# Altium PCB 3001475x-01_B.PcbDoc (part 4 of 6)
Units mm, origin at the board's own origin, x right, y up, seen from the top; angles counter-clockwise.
Board outline 335 x 91 mm, 12 copper layers (Top Layer, L2 GND, Layer 3, L4 GND, Layer 5, L6 PWR, L7 3V3, Layer 8, L9 GND, Layer 10, L11 GND, Bottom Layer), stack 1.59 mm thick; 339 components, 431 nets, 1732 pads, 1526 vias.
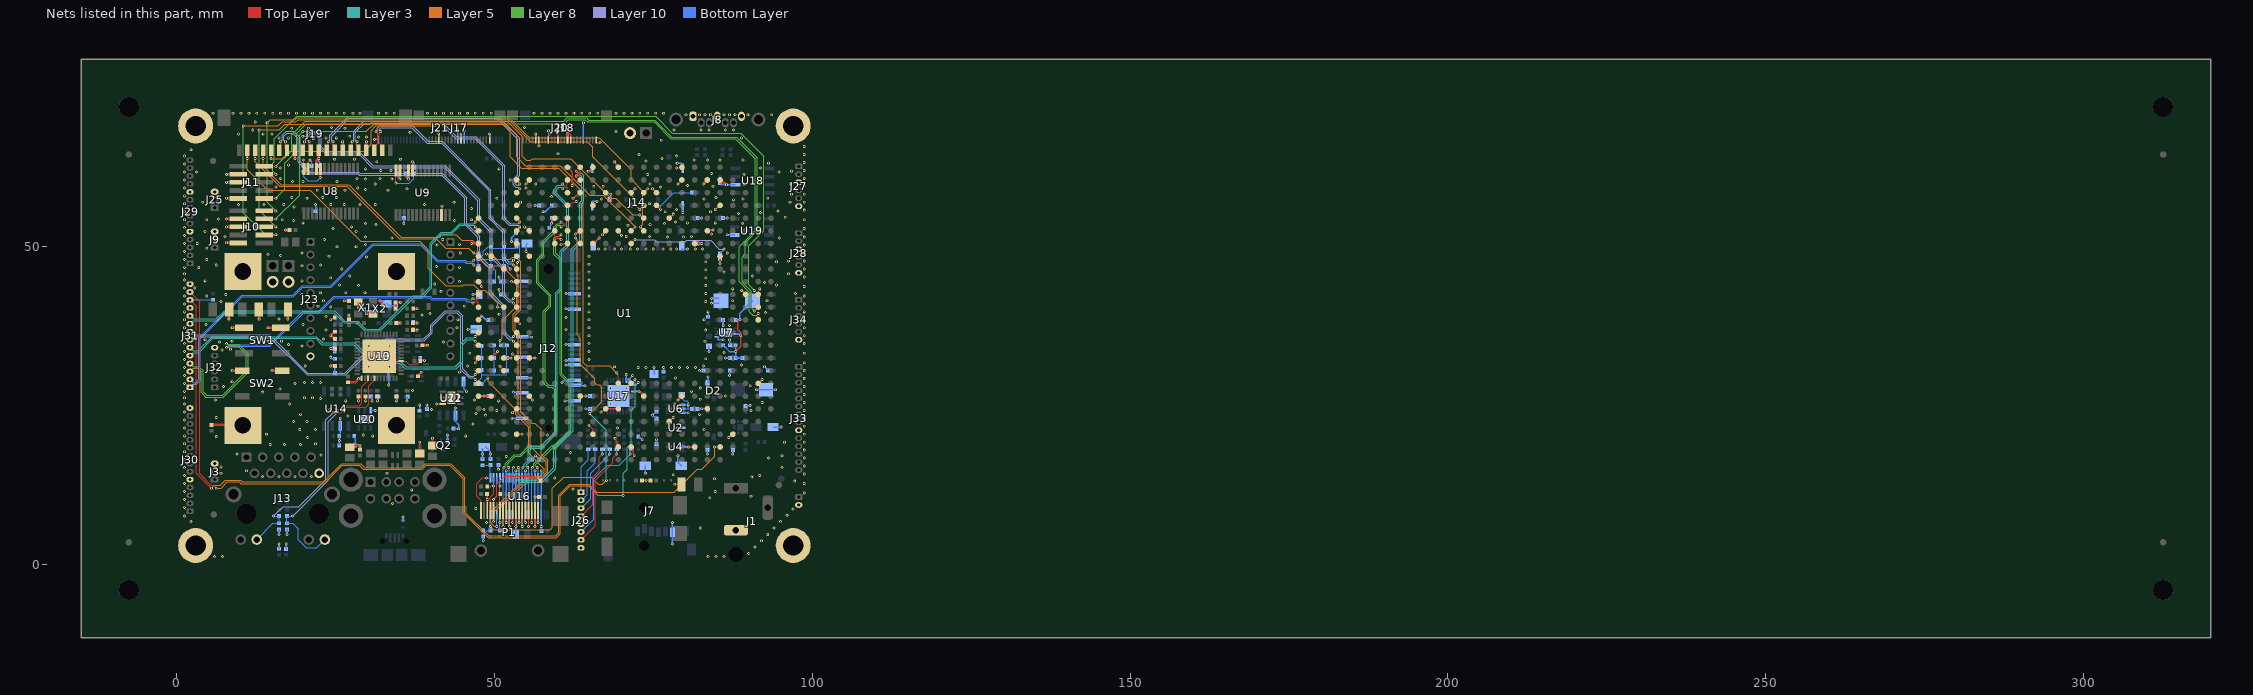
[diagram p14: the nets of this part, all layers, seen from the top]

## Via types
v1: diameter 0.45, hole 0.2, Top Layer to Bottom Layer, 1511 vias
v2: diameter 0.5, hole 0.2, Top Layer to Bottom Layer, 14 vias
v3: diameter 0.45/0.45/0.45/0.45/0.45/0.45/0.45/0.45/0.45/0.45/0.45/0.45 (per signal layer), hole 0.2, Top Layer to Bottom Layer, 1 vias

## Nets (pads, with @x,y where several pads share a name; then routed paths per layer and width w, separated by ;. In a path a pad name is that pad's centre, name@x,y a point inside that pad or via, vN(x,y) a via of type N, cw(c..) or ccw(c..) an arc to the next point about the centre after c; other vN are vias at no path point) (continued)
GND: C1.2 C2.1 C3.1 C4.1 C5.1 C6.1 C7.1 C8.2 C9.1 C10.1 C11.1 C12.1 C13.1 C24.2 C25.2 C26.2 C27.2 C28.1 C29.1 C30.1 C33.2 C34.2 C35.2 C36.2 C37.1 C38.1 C39.1 C40.1 C41.1 C42.1 C43.1 C44.1 C45.1 C46.1 C47.1 C48.1 C49.1 C50.1 C51.1 C52.1 C53.1 C54.1 C55.1 C56.1 C57.1 C58.1 C59.1 C60.1 C61.1 C62.1 C63.2 C64.2 C65.2 C66.1 C67.1 C68.1 C69.1 C70.1 C71.1 C72.1 C73.1 C74.1 C75.1 C76.1 C77.1 C78.1 C79.1 C80.1 C81.1 C82.1 C83.1 C84.1 C85.1 C86.1 C89.1 C90.1 C95.1 C96.1 C99.1 C100.1 C101.1 D1.K D2.A D4.K D5.K D6.K D10.1 J1.2 J2.2 J3.3 J4.2 J5.2 J6.2 J7.6 J7.9 J7.10 J8.1 J8.4 J8.7 J9.3 J10.3 J10.5 J10.9 J11.3 J11.5 J11.9 J12.4 J12.9 J12.15 J12.18 J12.21 J12.26 J12.27 J12.29 J12.34 J12.35 J12.37 J12.40 J12.43 J12.50 J13.10 J14.5 J14.11 J14.12 J14.13 J14.14 J14.15 J14.16 J17.1 J17.10 J17.17 J18.5 J18.8 J18.11 J18.16 J19.4 J19.7 J19.10 J19.13 J20.1 J20.9 J20.10 J20.13 J20.16 J20.19 J20.20 J21.1 J21.26 J21.28 J21.36 J23.10 J25.3 J26.5 J26.8 J27.3 J27.6 J28.3 J28.6 J29.5 J29.10 J30.5 J30.14 J31.11 J31.14 J32.6 J33.9 J34.6 L12.1 L13.1 L15.1 L27.1 P1.2 P1.5 P1.8 P1.11 P1.17 pad.0 Q2.S R5.1 R14.1 R17.2 R18.2 R19.2 R26.1 R27.1 R28.1 R29.1 R37.1 R42.1 R43.1 R46.1 R49.1 R50.1 R54.2 R56.2 R57.2 R59.2 R70.1 R71.1 R73.1 R74.1 R83.1 R84.1 R89.1 SW1.1 SW1.2 SW2.1 SW2.2 U1.A8 U1.A10 U1.A12 U1.A17 U1.AA16 U1.AB4 U1.AB10 U1.AB21 U1.AC12 U1.AC13 U1.AC18 U1.B5 U1.B17 U1.B19 U1.B20 U1.C9 U1.C11 U1.C13 U1.C14 U1.C15 U1.D4 U1.D8 U1.D10 U1.D20 U1.E7 U1.E16 U1.F5 U1.F9 U1.F11 U1.F12 U1.F19 U1.G1 U1.G4 U1.G8 U1.G10 U1.G18 U1.H5 U1.H20 U1.K1 U1.K4 U1.L22 U1.N1 U1.N4 U1.T1 U1.T2 U1.T4 U1.T5 U1.U3 U1.V23 U1.W1 U1.W2 U1.W5 U1.W9 U1.W14 U1.W17 U1.Y4 U1.Y11 U1.Y12 U1.Y19 U2.2 U4.2 U5.A U6.3 U7.1 U7.9 U8.25 U9.12 U9.25 U10.13 U10.29 U10.49 U12.4 U12.6 U13.11 U13.37 U14.6 U16.3 U16.5 U16.8 U16.11 U16.14 U16.25 U16.28 U16.31 U16.34 U16.36 U17.1 U17.3 U17.31 U17.32 U17.33 U18.2 U19.2 U20.3 U20.7 U21.3 U21.7 X1.2 X1.4 X2.2 X2.4 | length 340.6
  Top Layer w0.125: U10.29@35.325,32 36.021,32 36.609,31.413 37.788,31.413 C54.1@38.5,32.125
  Top Layer w0.15: J20.16@58.5,66.8 58.5,67.375 58.75,67.625 58.75,68 v1(58.5,68.25)
  Top Layer w0.25: v3(24.25,38.5) R49.1@24.895,38.875 ; R49.1@24.834,38.953 R49.1@24.895,39 ; L15.1@27.25,18.725 v1@28.85,18.725 ; v1(28.625,25.75) C50.1@28.625,26.415 ; C71.1@28.875,18.085 v1@28.875,18.725 ; v1(29.75,25.75) C46.1@29.75,26.415 ; v1(31.625,25.75) C51.1@31.625,26.415 ; v1(34.625,25.75) C52.1@34.625,26.415 ; L13.1@38.25,17.475 v1(38.25,19.25) ; L12.1@40.25,18.725 v1(40.25,19.875) ; v1(40.875,25.25) U21.3@41.8,25.25 ; J17.17@41.25,66.8 v1(41.25,67.75) ; U9.12@41.75,55.075 v1(41.75,56.375) ; J17.10@44.75,66.8 v1(44.75,67.75) ; v1(47,31.75) U1.T1@47.5,32.5 ; U1.W1@47.5,26.5 v1(48.375,26.5) U1.W2@49.5,26.5 ; P1.17@48.875,8.5 v1(48.875,10.25) C86.1@48.875,11.085 ; J17.1@49.25,66.8 v1(49.25,67.75) ; v1(51.875,6.625) P1.11@51.875,8.5 ; v1(52.675,44.5) U1.K4@53.5,44.5 ; v1(52.875,23.875) U1.Y4@53.5,24.5 ; v1(52.875,33.125) U1.T4@53.5,32.5 ; v1(53.375,6) P1.8@53.375,8.5 ; U1.AB4@53.5,20.5 v1(54.375,20.5) ; U1.D4@53.5,56.5 v1(54.125,57) ; v1(54.875,6.625) P1.5@54.875,8.5 ; v1(55,59.875) U1.B5@55.5,60.5 ; U1.T5@55.5,32.5 v1(56.375,32.5) ; v1(56.375,6) P1.2@56.375,8.5 ; v1(56.375,10.625) C82.1@57.04,10.625 ; J20.20@56.5,66.8 v1(56.5,67.75) ; v1(57,65.875) J20.19@57,66.8 ; v1(59,53.625) U1.E7@59.5,54.5 ; J20.13@60,66.8 v1(60,68.125) ; U1.D8@61.5,56.5 v1(62.875,57.125) ; U1.A8@61.5,62.5 62.25,61.75 v1(62.25,59.625) ; J20.10@61.5,66.8 v1(61.5,68.125) 62,67.625 J20.9@62,66.8 ; v1(62.375,57.625) U1.C9@63.5,58.5 ; U1.W9@63.5,26.5 v1(64.375,26.5) ; v1(64.75,61.875) U1.A10@65.5,62.5 ; v1(64.875,21.875) 65.5,21.25 U1.AB10@65.5,20.5 ; U1.D10@65.5,56.5 v1(66.125,57.125) ; J20.1@66,66.8 66,66.375 v1(66.625,66.375) ; v1(66.75,24) U1.Y11@67.5,24.5 U1.Y12@69.5,24.5 ; v1(67,51.875) U1.F11@67.5,52.5 ; U1.C11@67.5,58.5 v1(68.3,58.25) ; v1(68.875,63.375) U1.A12@69.5,62.5 ; v1(69,19.875) U1.AC12@69.5,18.5 ; U1.F12@69.5,52.5 v1(70,51.75) ; U1.AC13@71.5,18.5 v1(72,17.125) ; U1.C13@71.5,58.5 v1(72.125,59.125) ; C13.1@73.21,13.25 v1(73.875,13.25) C12.1@74.54,13.25 ; U1.C14@73.5,58.5 v1(74.125,59.125) ; v1(74.875,59.125) U1.C15@75.5,58.5 ; U1.AA16@77.5,22.5 v1(78.125,23.125) ; U1.E16@77.5,54.5 v1(78.125,55.125) ; v1(78.375,12.625) D1.K@79.45,12.625 ; v1(78.625,62.375) U1.A17@79.5,62.5 ; v1(78.875,59.875) U1.B17@79.5,60.5 ; v1(80.5,18.5) U1.AC18@81.5,18.5 ; U1.G18@81.5,50.5 v1(82.625,50.5) ; v1(82.625,24.5) U1.Y19@83.5,24.5 ; U1.F19@83.5,52.5 v1(84.375,52.625) ; v1(84.75,55.875) U1.D20@85.5,56.5 ; v1(85.5,47.375) U1.H20@85.5,48.5
  Top Layer w0.3: v1(46.375,50.5) U1.G1@47.5,50.5 ; U1.N1@47.5,38.5 v1(48,39.125) ; U1.K1@47.5,44.5 v1(48,43.75) ; U1.T2@49.5,32.5 v1(50.5,33.5) ; v1(50.875,31.2) U1.U3@51.5,30.5 ; v1(52.7,50.825) U1.G4@53.5,50.5 ; U1.N4@53.5,38.5 v1(54,37.875) ; v1(54.75,53.125) U1.F5@55.5,52.5 ; v1(55,49.25) U1.H5@55.5,48.5 ; U1.W5@55.5,26.5 v1(56,25.875) ; v1(60.5,50.375) U1.G8@61.5,50.5 ; v1(62.75,52) U1.F9@63.5,52.5 ; U1.G10@65.5,50.5 v1(66.5,51.375) ; v1(72.75,27.25) U1.W14@73.5,26.5 ; v1(78.875,25.875) U1.W17@79.5,26.5 ; v1(88.875,43.125) U1.L22@89.5,42.5 ; U1.V23@91.5,28.5 v1(92.125,29.125)
  Top Layer w0.4: C29.1@5.5,21.96 pad.0@10.39,21.96 ; v1(7.875,50.625) J10.9@9.678,50.625 ; v1(7.875,53.125) J10.5@9.718,53.125 ; v1(7.875,54.375) J10.3@9.698,54.375 ; v1(7.875,57.625) J11.9@9.678,57.625 ; v1(7.875,60.125) J11.5@9.718,60.125 ; v1(7.875,61.375) J11.3@9.698,61.375 ; v1(8.25,38.625) D6.K@8.25,40.075 ; v1(8.75,30.5) SW2.1@10.35,30.5 ; v1(8.75,37.25) SW1.1@10.6,37.25 ; v1(13,38.625) D5.K@13,40.05 ; v1(14.378,37.25) SW1.2@16.4,37.25 ; v1(15,30.5) SW2.2@16.65,30.5 ; v1(17.125,52.625) C101.1@17.79,52.625 ; v1(17.5,38.625) D4.K@17.5,40.075 ; v1(18.625,63.875) J19.13@18.625,65.2 ; U8.25@21.997,62.25 21.997,63.497 v1(22.375,63.875) J19.10@22.375,65.2 ; v1(24.25,31.25) C58.1@24.915,31.25 ; v1(24.25,34) C59.1@24.915,34 ; C45.1@24.915,35.5 v1(24.25,36) C42.1@24.915,36.625 ; J19.7@26.125,65.2 v1(26.125,66.5) ; v1(26.375,41.5) C28.1@27.125,41.5 ; C43.1@27,28.665 28.04,28.665 v1(28.625,29.25) U10.13@29.075,29.25 ; C44.1@27.125,38.585 v1(27.125,39.25) ; v1(28.625,40.375) X1.4@28.625,41.325 ; v1(29.85,39.45) X1.2@30.825,39.45 ; J19.4@29.875,65.2 v1(29.875,66.5) ; v1(31.992,41.5) C30.1@32.5,40.835 ; C61.1@34.46,40.25 C60.1@34.46,41.25 v1(35.25,41.25) ; C47.1@34.585,38 v1(35.25,38) ; v1(36.5,60.625) U9.25@36.5,61.975 ; C56.1@37.21,36.875 v1(37.875,36.875) ; C55.1@37.21,38 v1(37.875,38) ; R50.1@37.23,40.25 v1(37.875,40.25) ; C53.1@37.96,29.71 v1(38.5,30.25) ; C54.1@38.5,32.125 v1(39,32.125) ; C48.1@38.71,34.5 v1(39.5,34.5) ; v1(82.875,59.875) U1.B19@83.5,60.5 ; U1.B20@85.5,60.5 v1(86.5,59.75) ; v1(86.875,20) U1.AB21@87.5,20.5
  Bottom Layer w0.15: v1(58.5,68.25) 58.55,68.2 J18.5@58.55,66.85
  Bottom Layer w0.25: R46.1@16.125,2.48 v1(16.125,3.25) ; v1(16.125,4.75) R54.2@16.125,5.52 ; C33.2@17.25,2.46 v1(17.25,3.25) ; v1(17.375,4.75) R56.2@17.375,5.52 ; C24.2@21.875,55.585 v1(21.875,56.625) ; v1(22.375,63.875) 22.375,63.375 22.5,63.25 C26.2@22.5,62.71 ; v1(24.25,32.625) 24.5,32.375 C77.1@24.915,32.375 ; R73.1@24.895,33.5 v1(24.25,34) R74.1@24.895,34.625 ; C57.1@24.915,30.125 R71.1@24.915,31.23 ; C68.1@25.625,18.79 v1(25.625,19.5) C65.2@25.625,20.21 ; U14.6@25.75,21.81 v1(25.75,23) ; C65.2@25.76,20.425 U14.6@25.76,21.8 ; C72.1@27.125,38.585 v1(27.125,39.25) ; C70.1@28.085,20.125 C69.1@28.085,18.75 v1(28.875,18.75) ; C63.2@29.5,40.165 v1(29.85,39.45) ; U20.3@30.575,24.275 30.6,24.25 v1(31.25,24.25) ; v1(30.75,25.75) C73.1@30.75,26.415 ; v1(31.125,66.875) J21.1@31.675,66.875 ; v1(31.625,25.75) C78.1@31.625,26.415 ; v1(31.992,41.5) X2.4@32.65,41.5 ; X2.4@33.1,41.05 33.44,40.71 C64.2@34.5,40.71 ; v1@33.365,28.375 33.365,29.94 U13.11@33.375,29.95 ; C79.1@34.585,38 v1(35.25,38) ; v1(34.625,25.75) C74.1@34.625,26.415 ; D10.1@35.625,6.925 v1(35.625,7.5) ; v1(35.75,53.625) C25.2@35.75,54.54 ; C27.2@36.125,61.54 36.125,61 v1(36.5,60.625) ; v1(36.25,25.71) C49.1@36.25,26.375 ; C76.1@37.21,36.875 v1(37.875,36.875) ; R70.1@37.23,38 v1(37.875,38) ; C75.1@38.21,32.5 38.585,32.125 v1(39,32.125) ; C67.1@38.25,24.46 v1(38.25,25.125) ; C66.1@39.375,24.46 v1(39.375,25.125) ; Q2.S@42.625,19.44 v1(42.625,20.375) ; C62.1@43.585,21.375 v1(44.375,21.375) 44.375,22 43.885,22.49 U12.6@43.885,23.425 ; U12.6@43.875,23.435 v1(43.875,24.625) ; U12.6@43.885,23.435 U12.6@43.885,23.55 ; J21.26@44.25,66.8 v1(44.25,68.25) ; U12.4@45.155,28.825 45.155,27.72 v1(45.625,27.25) ; J21.28@45.25,66.8 v1(45.25,68.25) ; v1(45.875,37) C35.2@47.15,37 ; v1(46.625,42.5) C40.1@47.6,42.5 ; v1(48,39.125) 48.625,38.5 C39.1@49.04,38.5 ; R89.1@48.125,16.605 v1(48.125,17.375) C34.2@48.125,18.225 ; v1(48.25,3.75) C83.1@48.25,4.415 ; v1(48.375,26.5) R59.2@49.02,26.5 ; C34.2@48.625,18.5 49.375,17.75 v1(49.375,17.375) C85.1@49.375,16.585 ; J21.36@49.25,66.8 v1(49.25,67.75) ; v1(50.625,15) C38.1@50.625,15.665 ; v1(50.75,43.25) 50.75,42.79 C41.1@51.04,42.5 ; v1(50.75,45.25) 50.75,44.79 C37.1@51.04,44.5 ; v1(51.875,6.625) U16.14@51.875,7.85 U16.25@51.875,13.65 v1(51.875,14.75) ; v1(52.675,44.5) J12.4@54.3,44.5 ; v1(52.7,50.825) 52.697,51.427 R42.1@53.395,52.125 ; v1(52.75,23) J12.50@54.4,23 ; v1(53,27.125) J12.40@54.275,27.125 ; C80.1@53.35,4.75 53.35,5.975 v1(53.375,6) U16.11@53.375,7.85 U16.28@53.375,13.65 v1(53.375,14.75) ; J12.34@54.425,29.375 v1(55.75,29.375) ; J12.18@54.45,35.75 v1(55.875,35.75) ; J12.26@54.5,32.5 v1(56.375,32.5) ; v1(54.875,6.625) U16.8@54.875,7.85 U16.31@54.875,13.65 v1(54.875,14.75) ; v1(55,49.25) 55,50.35 C36.2@55.15,50.5 ; R57.2@55.98,16.5 v1(56.5,17.125) C84.1@57.04,16.5 ; v1(56.375,6) U16.5@56.375,7.85 v1(56.375,10.625) U16.34@56.375,13.65 v1(56.375,14.75) ; v1(56.375,56.5) R5.1@57.02,56.5 ; v1(57.375,14.75) U16.36@57.375,13.65 U16.3@57.375,7.85 v1(57.375,6) 57.375,5.29 C81.1@57.415,5.25 ; v1(57.625,55.5) 58.02,55.5 R84.1@59.02,56.5 ; R43.1@58.625,52.98 v1(59,53.625) R83.1@59,54.48 ; J18.8@60,66.8 v1(60,68.125) ; v1(60.625,28.625) 61,29 J12.35@62.6,29 ; v1(61.125,25.75) J12.43@62.55,25.75 ; v1(61.25,31.375) J12.29@62.575,31.375 ; v1(61.25,34.625) J12.21@62.575,34.625 ; v1(61.25,40.25) 61.3,40.2 J12.15@62.6,40.2 ; v1(61.25,42.625) 61.275,42.6 J12.9@62.6,42.6 ; J18.11@61.5,66.8 v1(61.5,68.125) ; J12.37@62.675,28.125 v1(64.25,28.125) ; J18.16@64,66.8 v1(64,69.5) ; v1(64.375,24.5) C89.1@65.04,24.5 ; v1(64.375,26.5) C95.1@65.04,26.5 ; v1(64.75,61.875) J14.13@65.39,61.875 ; J14.12@65.39,56.475 65.39,57.125 v1(66.125,57.125) ; J14.5@68.12,57.415 68.3,57.595 v1(68.3,58.25) ; U17.31@70.75,28.95 70.75,29.75 v1(70.75,29.875) ; U17.32@71.25,28.95 71.25,29.25 v1(71.75,29.75) ; U17.3@71.95,27.25 v1(72.75,27.25) ; U17.1@71.95,28.25 72.25,28.25 v1(72.625,28.625) ; C90.1@72.625,20.165 72.71,20.165 v1(73.25,19.625) ; v1@73.7,14.425 J7.9@73.7,15.55 ; L27.1@75.125,29.975 v1(75.125,31) ; C7.1@75.5,18.96 v1(75.5,19.625) ; C6.1@75.5,22.96 v1(74.875,23.5) C5.1@75.5,24.04 ; C96.1@76.625,30.335 v1(76.625,31) ; v1(78,3.25) J7.6@78,5.05 v1(78,6.625) ; v1(78.75,21.5) U2.2@79.6,21.5 ; v1(78.75,63.125) 79.375,63.125 79.61,62.89 J14.14@79.61,62.335 ; v1@78.875,17 78.875,16.075 J7.10@79.4,15.55 ; J14.16@79.5,49.625 v1(80.375,49.625) ; U4.2@79.6,18.5 v1(80.5,18.5) ; U6.3@79.625,23.875 v1(80.5,23.875) ; v1(79.625,55.375) J14.15@79.625,56.46 ; C4.1@81.96,24.5 v1(82.625,24.5) ; R29.1@81.98,50.5 v1(82.625,50.5) ; R28.1@81.98,54.5 v1(82.625,54.5) ; v1(82.25,30.5) R19.2@82.895,30.5 ; v1(83.5,17.375) R14.1@83.5,18.02 ; D2.A@83.625,28.6 v1(83.625,29.5) ; R26.1@83.625,38.855 R26.1@83.625,38.98 v1(83.625,39.75) ; v1(83.75,33.5) R27.1@83.75,34.325 ; v1(84.125,41.125) C8.2@85.3,41.125 ; v1(84.125,41.875) C8.2@85.3,41.875 ; U7.1@85.15,35.825 85.15,35.375 v1(86,35.375) ; v1(85.5,47.375) R37.1@85.5,48.02 ; C99.1@85.5,60.04 85.79,59.75 v1(86.5,59.75) U18.2@87.915,59.75 ; v1@85.96,37.665 C11.1@85.96,38.5 ; C100.1@85.96,54.5 v1(86.625,54.5) ; v1(86.375,32.5) C9.1@87.04,32.5 ; v1(86.625,51.875) U19.2@87.79,51.875 ; v1(87,29.75) R17.2@87.02,30.5 ; C10.1@87.04,34.5 v1@87.04,35.335 ; v1(87.5,17.375) C2.1@87.5,18.04 ; C3.1@89.54,25 v1(90.25,25) ; v1(91.25,27.5) U5.A@92.7,27.5 v1(94.2,27.5) ; v1(92.5,31.125) R18.2@93.02,30.605 ; C1.2@93.85,21.625 v1(95.125,21.625)
  Bottom Layer w0.3: v1(61.25,32.125) 62.525,32.125 J12.27@62.6,32.2 ; J14.11@65.55,50.125 65.55,50.425 v1(66.5,51.375)
  Bottom Layer w0.4: v1(24.25,31.25) R71.1@24.895,31.25 ; v1(29.85,39.45) X2.2@30.9,39.45
  other v1: 6,1.25 7.25,1.25 83.625,1.25 84.875,1.25 86.125,1.25 90,1.75 91,2.75 92,3.75 93,4.75 82.375,5.75 94,5.75 48.75,6.625 2.25,6.75 95,6.75 1.25,7.625 96,7.75 97,8.75 47.075,8.825 1.25,9 34,9.625 1.25,10.25 83.875,10.5 90.375,10.75 98.75,11.25 1.25,11.5 84.75,11.5 37,11.75 62.375,11.875 1.25,12.75 98.75,12.75 97.25,13.125 84.625,13.5 59.5,13.625 90.5,13.75 13.5,13.875 16.125,13.875 18.625,13.875 21.25,13.875 1.25,14 91.75,14 78.125,14.125 98.75,14.25 7,14.375 33.125,14.375 73.75,14.375 11,14.75 1.25,15.25 95.25,15.25 7,15.375 98.75,15.5 1.25,16.5 93.125,16.75 98.75,16.75 51.875,17 78.875,17.125 95.25,17.125 22.75,17.25 9.5,17.375 62,17.625 1.25,17.75 98.75,18 14.75,18.875 17,18.875 19.5,18.875 1.25,19 21.875,19 95.625,19.25 98.75,19.25 20.625,20 6.25,20.125 1.25,20.25 30.875,20.25 45.5,20.25 29.375,20.375 58.375,20.375 14.125,20.5 98.75,20.5 19.375,21.25 21.875,21.25 83,21.25 1.25,21.5 69.375,21.5 98.75,21.75 46.625,22.125 18.375,22.5 20.5,22.5 1.25,22.75 29.625,22.875 98.75,23 6.25,23.125 27,23.375 48.625,23.5 19.5,23.625 82.25,23.625 47.125,23.75 1.25,24 50.375,24.25 90.375,24.25 98.75,24.25 24.125,24.375 40.125,24.375 48.375,24.375 1.25,25.25 17.75,25.25 68.25,25.25 78.375,25.25 92.125,25.5 98.75,25.5 26.625,25.75 50.625,25.75 6.125,25.875 46.875,25.875 82.375,26 22.625,26.125 1.25,26.25 20.125,26.25 21.375,26.25 43.25,26.25 86.375,26.5 98.75,26.75 13.5,27.125 1.25,27.25 81,27.25 37.125,27.375 16.25,27.625 70.75,27.75 82.375,27.75 7.375,28 98.75,28 14.375,28.125 90.25,28.125 33.375,28.25 1.25,28.5 18.625,28.5 20.125,28.625 21.375,28.625 22.625,28.625 8.75,28.75 98.75,29.25 78.5,29.375 1.25,29.75 44.5,30.25 98.75,30.5 1.25,31 72.625,31 73.875,31 77.875,31 79.125,31 80.375,31 81.625,31 68.875,31.125 20.25,31.25 45.75,31.25 82.875,31.25 88.875,31.375 98.75,31.75 1.25,32.25 64.875,32.25 83.25,32.375 46.125,33.25 98.75,33.25 86.125,33.375 1.25,33.5 64.875,33.525 7.125,33.75 8.5,33.875 19.75,34.375 17.625,34.625 1.25,34.75 64.875,34.75 98.75,34.75 6.75,35 42,35 8.75,35.125 14.375,35.125 16.5,35.125 83.125,35.125 4.5,35.375 87,35.375 23.125,35.5 1.25,36 64.875,36 98.75,36 86.5,36.125 23.5,36.875 83.25,36.875 86.5,36.875 61.25,37 1.25,37.25 44.125,37.25 64.875,37.25 98.75,37.25 86,37.625 87,37.625 4.625,37.75 19.875,37.75 1.25,38.5 44.25,38.5 64.875,38.5 83,38.5 98.75,38.5 16.125,38.625 61.25,38.875 23.5,39 38.625,39.25 50.75,39.375 39.875,39.5 92.625,39.625 1.25,39.75 64.875,39.75 98.75,39.75 24.25,40.5 22.25,40.625 45.25,40.625 1.25,41 64.875,41 98.75,41 19.75,41.25 7,41.375 83.25,41.375 23.125,41.5 87.5,41.5 92.875,41.5 1.25,42.25 4.75,42.25 64.875,42.25 98.75,42.25 7.75,42.5 19.75,42.5 83.25,42.625 97.375,42.625 22.625,42.75 26.625,42.75 29.625,42.75 41.625,43 87.5,43.375 91.75,43.375 1.25,43.5 2.875,43.5 64.875,43.5 98.75,43.75 28.625,43.875 83.25,43.875 25.625,44 94.375,44 40.625,44.125 92.5,44.375 44.5,44.5 4.5,44.625 19.75,44.625 1.25,44.75 64.875,44.75 24.25,45.125 83.25,45.125 98.75,45.25 27.25,45.375 90.625,45.375 1.25,45.75 96.25,45.75 64.875,46 86.125,46 83.25,46.375 26,46.5 98.75,46.5 1.25,46.75 3.5,46.75 44.5,46.75 40.875,46.875 19.75,47 6.25,47.125 22.625,47.125 64.875,47.25 83.25,47.625 94.375,47.625 96.25,47.75 98.75,47.75 1.25,48 4.75,48 29.875,48.375 24,48.5 64.875,48.5 16.375,48.625 14.375,48.75 19.75,49 44.625,49 86.625,49 98.75,49 1.25,49.25 66.375,49.625 67.375,49.625 68.875,49.625 70,49.625 71.375,49.625 72.5,49.625 73.875,49.625 75,49.625 76.5,49.625 77.75,49.625 78.625,49.625 81.625,49.625 82.75,49.625 4.75,49.75 25.25,50 28.25,50 41,50.25 98.75,50.25 29.75,50.375 44.5,50.375 1.25,50.5 3.25,50.5 23.25,51.125 41.875,51.125 33.875,51.375 94.875,51.375 29.75,51.5 77.25,51.5 79.75,51.5 98.75,51.5 7.625,51.625 70.75,51.625 74.375,51.625 81,51.625 1.25,51.75 84.125,52 4.5,52.375 28.25,52.375 24.625,52.875 98.75,52.875 1.25,53 27.5,53.125 71,53.375 31.375,53.5 74.5,53.5 29.75,53.625 76.75,53.625 89,53.625 19.875,53.75 80.375,53.75 84.75,53.75 78.5,53.875 18.375,54.125 43.75,54.125 1.25,54.25 4.75,54.25 16.625,54.25 46.375,54.25 98.75,54.25 6.625,54.375 95.75,54.625 88.375,55.25 91.875,55.375 1.25,55.5 76.875,55.5 84,55.5 94.625,55.625 98.75,55.75 78.625,55.875 46.375,56 18.5,56.25 9.75,56.625 13.75,56.625 16.875,56.625 24.25,56.625 26.375,56.625 28.875,56.625 31.25,56.625 39,56.625 1.25,56.75 74.375,56.75 4.125,57 43.625,57 96.5,57 98.75,57 87.625,57.375 66.875,57.5 83,57.5 89.125,57.5 20.5,57.625 50.375,57.625 93,57.625 18.125,57.75 23,57.75 25.125,57.75 84.875,57.75 59,57.875 1.25,58 96.75,58.25 98.75,58.25 22.125,58.875 25.125,58.875 26.5,58.875 33.25,58.875 29.75,59 36.25,59.125 1.25,59.25 28.5,59.25 55,59.25 15.625,59.375 76.125,59.375 11.75,59.5 65.625,59.5 67.125,59.5 84.375,59.5 98.75,59.5 80.375,59.625 89.25,59.75 31.25,59.875 56.5,59.875 74.5,59.875 96.625,59.875 18.25,60.25 19.875,60.25 25.25,60.25 1.25,60.5 52.5,60.5 29.75,60.625 33.875,60.625 16.375,60.75 28.375,60.75 32,60.75 98.75,60.75 74.125,61.375 89.25,61.375 84.125,61.5 1.25,61.75 3.125,61.75 94.75,61.75 96.75,61.875 32.125,62 33.75,62 98.75,62 29.75,62.25 50.75,62.25 16.375,62.375 91.875,62.375 17.625,62.875 1.25,63 93.125,63.125 98.75,63.25 31.5,63.375 73.875,63.5 81.375,63.625 83.5,63.625 85.5,63.625 89.125,63.625 24.875,63.75 28,63.75 35.25,63.75 76.375,63.875 1.25,64.25 78.625,64.25 72.75,64.5 98.75,64.5 60,64.625 2.25,65.25 98.75,65.75 76.25,66.75 21.5,67 16.125,67.125 17.625,67.125 23.5,67.125 25.125,67.125 88.875,67.125 28.625,67.25 29.875,67.25 19.875,67.375 27.25,67.375 9.75,67.75 13.625,67.75 15,67.75 36.75,68 69.125,68.125 40.875,68.25 12,68.375 78.25,68.375 82.5,68.375 83.75,68.375 86.375,68.375 87.625,68.375 18.125,68.625 20.75,68.625 26.5,68.625 24.375,68.75 54.75,68.75 60.375,68.875 12.375,69.625 80.125,70.75 82.25,70.75 83.125,70.75 84,70.75 86.125,70.75 87,70.75 87.875,70.75 89.875,70.75 93.625,70.75 5.75,71 8.875,71 10.125,71 11.375,71 12.625,71 13.875,71 15.125,71 16.375,71 17.625,71 18.875,71 20.125,71 21.375,71 22.625,71 23.875,71 25.125,71 26.375,71 27.75,71 28.875,71 31.75,71 33,71 34.25,71 39.5,71 40.75,71 42,71 43.25,71 44.5,71 45.75,71 47,71 48.25,71 49.5,71 56.25,71 57.5,71 58.75,71 60,71 61.25,71 62.5,71 63.75,71 65,71 66.25,71 69.125,71 70.375,71 71.625,71 72.875,71 74.125,71 75.375,71 76.625,71
  other v2: 68.25,27.75 30.25,31.125 33.5,31.125 31.875,32.75 30.25,34.375 33.5,34.375
HDMI_CEC_IN: R88.2 U1.H2 U16.16 | length 57.7
  Top Layer w0.125: v1(48.75,48.875) U1.H2@49.5,48.5
  Layer 5 w0.125: v1(48.75,48.875) 49.5,48.875 50.375,48 52.5,48 52.875,48.375 53.375,48.375 54.125,47.625 54.125,40.125 53.25,39.25 53.25,36.875 54.125,36 54.125,24 55.875,22.25 56.375,22.25 57.375,21.25 57.375,17.375 58.375,16.375 58.375,14.375 57.375,13.375 55.375,13.375 50.875,8.875 v1(50.875,6.602)
  Bottom Layer w0.125: R88.2@50.875,5.27 R88.2@50.875,5.355 v1(50.875,6.602) U16.16@50.875,7.85
HDMI_CLK_N: P1.12 U1.E8 U16.15 U16.24 | length 61.5
  Top Layer w0.122: v1(51.375,6) P1.12@51.375,8.5 ; v1(60.5,53.875) 60.748,53.628 61.375,53.628 61.5,53.753 U1.E8@61.5,54.5
  Layer 8 w0.101: v1(51.5,15.25) 51.725,15.475 51.725,15.874 53.151,17.3 54.05,17.3 55.425,18.675 57.376,18.675 59.5,20.799 59.5,27.5 59.125,27.875 58.451,27.875 57.7,28.626 57.7,39.874 58.6,40.775 58.6,42.275 56.625,44.25 56.625,47.925 57.5,48.8 57.5,50.75 59.325,52.575 59.325,53.099 59.876,53.65 60.275,53.65 v1(60.5,53.875)
  Bottom Layer w0.122: v1(51.375,6) U16.15@51.375,7.85 U16.24@51.375,13.65 51.375,15.125 v1(51.5,15.25)
HDMI_CLK_P: P1.10 U1.F8 U16.13 U16.26 | length 61
  Top Layer w0.122: v1(52.375,6) P1.10@52.375,8.5 ; v1(60.5,53.125) 60.748,53.372 61.375,53.372 61.5,53.247 U1.F8@61.5,52.5
  Layer 8 w0.101: v1(52.25,15.25) 52.025,15.475 52.025,15.75 53.275,17 54.174,17 55.549,18.375 57.5,18.375 59.8,20.675 59.8,27.624 59.249,28.175 58.575,28.175 58,28.75 58,39.75 58.9,40.65 58.9,42.399 56.925,44.374 56.925,47.801 57.8,48.676 57.8,50.626 59.625,52.451 59.625,52.975 60,53.35 60.275,53.35 v1(60.5,53.125)
  Bottom Layer w0.122: v1(52.25,15.25) 52.375,15.125 U16.26@52.375,13.65 U16.13@52.375,7.85 v1(52.375,6)
HDMI_D0_N: P1.9 U1.A9 U16.12 U16.27 | length 70.8
  Top Layer w0.122: v1(52.875,6.625) P1.9@52.875,8.5 ; v1(62.875,61.875) 63.122,61.628 63.375,61.628 63.5,61.753 U1.A9@63.5,62.5
  Layer 3 w0.101: v1(53,15.25) 52.875,15.125 52.875,14.5 53.225,14.15 53.225,13.751 54.026,12.95 57.499,12.95 59.625,15.076 59.625,18.326 62.375,21.076 62.375,49.45 63.712,50.787 63.712,56.788 64.05,57.126 64.05,61.224 63.624,61.65 63.1,61.65 v1(62.875,61.875)
  Bottom Layer w0.122: v1(52.875,6.625) U16.12@52.875,7.85 U16.27@52.875,13.65 52.875,15.125 v1(53,15.25)
HDMI_D0_P: P1.7 U1.B9 U16.10 U16.29 | length 69.3
  Top Layer w0.122: v1(53.875,6.625) P1.7@53.875,8.5 ; v1(62.875,61.125) 63.123,61.373 63.378,61.373 63.5,61.25 U1.B9@63.5,60.5
  Layer 3 w0.101: v1(53.75,15.25) 53.875,15.125 53.875,14.5 53.75,14.375 53.525,14.15 53.525,13.875 54.15,13.25 57.375,13.25 59.325,15.2 59.325,18.45 62.075,21.2 62.075,49.574 63.412,50.911 63.412,56.912 63.75,57.25 63.75,61.1 63.5,61.35 63.1,61.35 v1(62.875,61.125)
  Bottom Layer w0.122: v1(53.75,15.25) 53.875,15.125 U16.29@53.875,13.65 U16.10@53.875,7.85 v1(53.875,6.625)
HDMI_D1_N: P1.6 U1.B8 U16.9 U16.30 | length 63.6
  Top Layer w0.122: v1(54.375,6) P1.6@54.375,8.5 ; v1(60.75,59.875) 60.998,59.628 61.375,59.628 61.5,59.753 U1.B8@61.5,60.5
  Layer 3 w0.101: v1(54.5,15.25) 54.725,15.475 54.725,15.749 55.325,16.349 55.325,18.2 55.75,18.625 57.325,18.625 59.625,20.925 59.625,42.749 60.325,43.449 60.325,49.249 61.375,50.299 61.375,56.326 59.325,58.376 59.325,58.974 60.001,59.65 60.525,59.65 v1(60.75,59.875)
  Bottom Layer w0.122: v1(54.375,6) U16.9@54.375,7.85 U16.30@54.375,13.65 54.375,15.125 v1(54.5,15.25)
HDMI_D1_P: P1.4 U1.C8 U16.7 U16.32 | length 63.1
  Top Layer w0.122: v1(55.375,6) P1.4@55.375,8.5 ; v1(60.75,59.125) 60.998,59.372 61.375,59.372 61.5,59.247 U1.C8@61.5,58.5
  Layer 3 w0.101: v1(55.25,15.25) 55.025,15.475 55.025,15.625 55.625,16.225 55.625,18.076 55.874,18.325 57.449,18.325 59.925,20.801 59.925,42.625 60.625,43.325 60.625,49.125 61.675,50.175 61.675,56.45 59.625,58.5 59.625,58.85 60.125,59.35 60.525,59.35 v1(60.75,59.125)
  Bottom Layer w0.122: v1(55.25,15.25) 55.375,15.125 U16.32@55.375,13.65 U16.7@55.375,7.85 v1(55.375,6)
HDMI_D2_N: P1.3 U1.F7 U16.6 U16.33 | length 53.4
  Top Layer w0.122: v1(55.875,6.625) P1.3@55.875,8.5 ; U1.F7@59.5,52.5 59.5,51.752 59.625,51.628 60.253,51.628 v1(60.5,51.875)
  Layer 8 w0.101: v1(56,15.25) 56.225,15.475 56.225,15.874 59.026,18.675 59.376,18.675 61.75,21.049 61.75,28.451 60.325,29.876 60.325,47.875 59.375,48.825 59.375,51.299 59.726,51.65 60.275,51.65 v1(60.5,51.875)
  Bottom Layer w0.122: v1(55.875,6.625) U16.6@55.875,7.85 U16.33@55.875,13.65 55.875,15.125 v1(56,15.25)
HDMI_D2_P: P1.1 U1.G7 U16.4 U16.35 | length 52.9
  Top Layer w0.122: v1(56.875,6.625) P1.1@56.875,8.5 ; U1.G7@59.5,50.5 59.5,51.248 59.625,51.373 60.253,51.373 v1(60.5,51.125)
  Layer 8 w0.101: v1(56.75,15.25) 56.525,15.475 56.525,15.75 59.15,18.375 59.5,18.375 62.05,20.925 62.05,28.575 60.625,30 60.625,47.999 59.675,48.949 59.675,51.175 59.85,51.35 60.275,51.35 v1(60.5,51.125)
  Bottom Layer w0.122: v1(56.75,15.25) 56.875,15.125 U16.35@56.875,13.65 U16.4@56.875,7.85 v1(56.875,6.625)
HDMI_DDC_SCL: P1.15 R87.1 U16.22 | length 15.6
  Top Layer w0.125: P1.15@49.875,8.5 v1(49.875,10.25) 50.375,10.75 50.375,12.625 51.625,13.875 56.125,13.875 56.75,13.25 R87.1@57.27,13.25
  Bottom Layer w0.125: v1(49.875,10.25) 50.375,10.75 U16.22@50.375,13.65
HDMI_DDC_SDA: P1.16 R85.1 U16.21 | length 6.4
  Top Layer w0.125: R85.1@48.855,12.25 49.375,12.25 49.5,12.375 v1(49.875,12.375) 49.875,11.125 49.375,10.625 P1.16@49.375,8.5
  Bottom Layer w0.125: v1(49.875,12.375) U16.21@49.875,13.65
HDMI_HPD: C83.2 R90.2 U1.G9 U16.19 | length 72.9
  Top Layer w0.125: v1(62.75,51.375) U1.G9@63.5,50.5
  Layer 5 w0.125: v1(49.375,6) 49.875,5.5 58.75,5.5 59.125,5.875 59.125,12 60.875,13.75 65.25,13.75 66.375,12.625 67,12.625 v1(67.625,13.25) ; v1(62.75,51.375) 63,51.125 63,36.125 63.5,35.625 63.5,31.5 65.75,29.25 65.75,28.625 66.125,28.25 66.5,28.25 66.875,27.875 66.875,25.625 v1(65,23.75)
  Layer 3 w0.125: v1(65,23.75) 67.625,21.125 v1(67.625,13.25)
  Bottom Layer w0.125: C83.2@48.27,5.355 R90.2@49.375,5.355 v1(49.375,6) U16.19@49.375,7.85
HDMI_I2C_SCL: R99.2 U16.17 | length 35.8
  Layer 5 w0.125: v1(49,29.375) 49,28.75 53.375,24.375 53.375,23.625 55.375,21.625 55.375,19 ; v1(50.375,6) 50,6 49.375,6.625 49.375,8.125 55.125,13.875 57.168,13.875 57.875,14.582 57.875,15 55.375,17.5 55.375,19 ; 55.286,19.089 55.375,19
  Bottom Layer w0.125: R99.2@47.98,28.375 48.98,29.375 v1(49,29.375) ; v1(50.375,6) U16.17@50.375,7.85
HDMI_I2C_SDA: R100.2 U16.18 | length 52.9
  Layer 5 w0.125: v1@49.875,6.625 v1(49.875,6.75) 49.875,8.25 55.25,13.625 57.271,13.625 58.125,14.479 58.125,16.125 55.625,18.625 55.625,21.875 53.75,23.75 53.75,36 53,36.75 53,39.375 53.75,40.125 53.75,45.375 53.625,45.5 v1(53.625,47.5)
  Bottom Layer w0.125: v1(49.875,6.75) U16.18@49.875,7.85 ; R100.2@53.5,50.98 54,50.48 54,47.875 v1(53.625,47.5)
HDMICEC: P1.13 R86.2 U16.23 | length 5.1
  Top Layer w0.125: P1.13@50.875,8.5 v1(50.875,12.375)
  Bottom Layer w0.125: v1(50.875,12.375) U16.23@50.875,13.65
HDMIHPD: C85.2 P1.19 R89.2 U16.20 | length 10.2
  Top Layer w0.125: P1.19@47.875,8.5 47.875,10.125 47.25,10.75 47.25,12.75 48.125,13.625 v1(48.75,13.625)
  Bottom Layer w0.125: R89.2@48.125,15.645 C85.2@49.355,15.645 ; v1(48.75,13.625) U16.20@49.35,13.625 ; U16.20@49.375,13.65 C85.2@49.375,15.645
I2C3_SCL: R95.1 R97.1 R99.1 R101.1 R103.1 R106.1 R108.1 R109.1 R112.1 R114.1 U1.T3 | length 21.3
  Top Layer w0.125: U1.T3@51.5,32.5 v1@52.625,32.5
  Bottom Layer w0.125: R99.1@47.02,28.375 48,29.355 48,29.855 ; R108.1@47.98,34.375 R114.1@47.98,30.625 47.98,29.875 49.98,29.875 ; R106.1@49.98,34.5 R103.1@49.98,32.5 R101.1@49.98,30.5 49.98,29.875 ; R97.1@51.98,34.5 R95.1@51.98,32.5 ; v1(52.625,32.5) R95.1@51.98,32.5 ; 49.98,29.875 51.875,29.875 51.98,29.98 R109.1@51.98,30.5 R95.1@51.98,32.5
I2C3_SDA: R96.1 R98.1 R100.1 R102.1 R105.1 R107.1 R110.1 R111.1 R113.1 R115.1 U1.J3 | length 19.4
  Top Layer w0.125: U1.J3@51.5,46.5 v1(52.5,46.5)
  Bottom Layer w0.125: R115.1@47.5,46.98 R98.1@47.5,48.02 ; R110.1@49.5,50.02 49.02,50.02 48.25,49.25 48.25,48.77 R98.1@47.5,48.02 ; R110.1@49.558,49.962 49.725,49.795 53.275,49.795 R100.1@53.5,50.02 ; R107.1@49.98,44.5 50.25,44.77 50.25,46.23 R111.1@49.5,46.98 R102.1@49.5,48.02 ; v1(52.5,46.5) 52.02,46.98 R96.1@51.5,46.98 R105.1@51.5,48.02 R102.1@49.5,48.02 ; R98.1@47.5,48.02 R102.1@49.5,48.02
JTAG_MOD: R37.2 U1.G13 | length 16.6
  Top Layer w0.125: U1.G13@71.5,50.5 v1(72.125,51.125)
  Layer 10 w0.125: v1(72.125,51.125) 75.125,51.125 75.5,50.75 80,50.75 80.25,51 84,51 85.375,49.625 v1(86.125,49.625)
  Bottom Layer w0.125: R37.2@85.5,48.98 v1@86.125,49.605
JTAG_TCK: J10.4 U1.F13 | length 79.9
  Top Layer w0.125: J10.4@13.802,54.375 v1(15.625,54.375) ; U1.F13@71.5,52.5 v1(72.125,53.125)
  Layer 8 w0.125: v1(15.625,54.375) 19.375,58.125 19.375,67.625 v1(19.875,68.125)
  Layer 5 w0.125: v1(19.875,68.125) 29.875,68.125 31,69.25 40.375,69.25 40.625,69.5 51.625,69.5 53.5,67.625 53.5,64.125 54.875,62.75 60.375,62.75 65,58.125 67.125,58.125 v1(72.125,53.125)
JTAG_TDI: J10.8 U1.D14 | length 92.9
  Top Layer w0.125: J10.8@13.802,51.875 v1(15.625,51.875) ; v1(72.875,55.875) U1.D14@73.5,56.5
  Layer 8 w0.125: v1(10.5,69) 10.5,55.375 14,51.875 v1(15.625,51.875)
  Layer 5 w0.125: v1(10.5,69) 16,69 16.625,69.625 18.75,69.625 19.125,70 52.25,70 55.75,66.5 64.625,66.5 65.5,65.625 65.5,64.125 72,57.625 72,56.75 v1(72.875,55.875)
JTAG_TDO: J10.6 U1.E14 | length 87.6
  Top Layer w0.125: J10.6@13.782,53.125 v1(15.625,53.125) ; v1(72.875,55) U1.E14@73.5,54.5
  Layer 8 w0.125: v1(13,68.375) 13,55.75 v1(15.625,53.125)
  Layer 5 w0.125: v1(13,68.375) 16.125,68.375 17,69.25 30.375,69.25 30.625,69.5 40.125,69.5 40.375,69.75 52,69.75 54.375,67.375 54.375,64.25 55,63.625 55.75,63.625 56,63.875 62.042,63.875 68.292,57.625 69.125,57.625 71.75,55 v1(72.875,55)
JTAG_TMS: J10.2 U1.F14 | length 87.9
  Top Layer w0.125: J10.2@13.822,55.625 v1(15.625,55.625) ; v1(73,53.125) U1.F14@73.5,52.5
  Layer 8 w0.125: v1(14.25,69.5) 14.25,57 v1(15.625,55.625)
  Layer 5 w0.125: v1(14.25,69.5) 14.75,70 18.625,70 18.875,70.25 52.375,70.25 55.5,67.125 66.5,67.125 71.5,62.125 71.5,60.625 73.375,58.75 73.375,53.5 v1(73,53.125)
JTAG_TRST_N: R36.1 U1.D15 | length 7.2
  Top Layer w0.125: U1.D15@75.5,56.5 v1(76.125,55.875)
  Bottom Layer w0.125: v1(76.125,55.875) 76.125,56.375 78.25,58.5 R36.1@81.02,58.5
LED1/PHYAD0: J13.D2 R53.1 R54.1 U10.17 | length 38.8
  Top Layer w0.125: v1(24.625,23.875) 25.875,23.875 26.75,24.75 29.75,24.75 30.25,25.25 30.25,28.125 31.125,29 U10.17@31.125,29.3
  Layer 10 w0.125: v1(15.25,7.625) 16.75,9.125 19.25,9.125 23.5,13.375 23.5,22.75 v1(24.625,23.875)
  Bottom Layer w0.125: J13.D2@12.626,3.936 15.17,6.48 R54.1@16.125,6.48 R53.1@16.125,7.625 ; v1(15.25,7.625) R53.1@16.105,7.625
LED2/PHYAD1: J13.D4 R55.1 R56.1 U10.15 | length 39.5
  Top Layer w0.125: v1(25.125,24.375) 25.75,24.375 26.375,25 28.75,25 29.125,25.375 29.125,28 30.125,29 U10.15@30.125,29.3
  Layer 10 w0.125: v1(18.25,7.625) 23.875,13.25 23.875,22.5 25.125,23.75 v1(25.125,24.375)
  Bottom Layer w0.125: R55.1@17.375,7.625 R56.1@17.375,6.48 18.27,6.48 19.125,5.625 19.125,3.875 20.375,2.625 22.033,2.625 J13.D4@23.344,3.936 ; R55.1@17.395,7.625 v1(18.25,7.625)
LINE_IN_L: J26.4 L21.1 | length 11.9
  Top Layer w0.125: J26.4@63.625,7.625 65.5,9.5 65.5,13.75 66.5,14.75 66.5,16.875 v1(67,17.375)
  Bottom Layer w0.125: v1(67,17.375) L21.1@67,18.145
LINE_IN_R: J26.3 L20.1 | length 11.1
  Bottom Layer w0.125: J26.3@63.625,8.875 65.125,10.375 65.125,14.375 v1(68.125,17.375) L20.1@68.125,18.145
LINE_OUT_L: J26.7 L19.2 | length 16.6
  Top Layer w0.125: J26.7@63.625,3.875 65.875,6.125 65.875,13.25 68.625,16 68.625,16.75 v1(69.25,17.375)
  Bottom Layer w0.125: v1(69.25,17.375) L19.2@69.25,18.145
LINE_OUT_R: J26.6 L18.2 | length 17.4
  Bottom Layer w0.125: J26.6@63.625,5.125 65.625,7.125 65.625,13.5 67.75,15.625 69.625,15.625 v1(71.375,17.375) 71.375,18.02 L18.2@71.5,18.145
LVDS0_CLK_N: J19.11 U1.M4 | length 54
  Top Layer w0.122: v1(20.875,66.5) 20.875,65.45 J19.11@21.125,65.2 ; v1(53,41.125) U1.M4@53.5,40.5
  Layer 10 w0.101: v1(20.875,66.5) 20.65,66.725 20.65,67.25 21.15,67.75 21.875,67.75 22.45,67.175 22.45,65.626 23.626,64.45 28.8,64.45 30.8,62.45 42.175,62.45 47.375,57.25 47.375,54.326 49.325,52.376 49.325,48.425 51.325,46.425 51.325,42.276 52.251,41.35 52.775,41.35 v1(53,41.125)
LVDS0_CLK_P: J19.12 U1.L4 | length 54.5
  Top Layer w0.122: J19.12@19.875,65.2 20.125,65.45 v1(20.125,66.5) ; v1(53,41.875) U1.L4@53.5,42.5
  Layer 10 w0.101: v1(20.125,66.5) 20.35,66.725 20.35,67.374 21.026,68.05 21.999,68.05 22.75,67.299 22.75,65.75 23.75,64.75 28.924,64.75 30.924,62.75 42.299,62.75 47.675,57.374 47.675,54.45 49.625,52.5 49.625,48.549 51.625,46.549 51.625,42.4 52.375,41.65 52.775,41.65 v1(53,41.875)
LVDS0_CONTRAST: J19.16 U1.V12 | length 95.2
  Top Layer w0.125: v1(14.875,63.875) J19.16@14.875,65.2 ; v1(69.25,30.125) 69.5,29.875 U1.V12@69.5,28.5
  Layer 5 w0.125: v1(14.875,63.875) 16.625,63.875 17.75,65 29.5,65 30.625,66.125 30.625,68.25 31.375,69 40.75,69 41,69.25 51.5,69.25 52.5,68.25 52.5,64.125 54.25,62.375 60.125,62.375 64,58.5 64,31.75 64.5,31.25 68.125,31.25 v1(69.25,30.125)
LVDS0_I2C_SCL: J19.17 R97.2 | length 62.5
  Top Layer w0.125: v1(13.625,63.875) J19.17@13.625,65.2
  Layer 5 w0.125: v1(13.625,63.875) 13.625,62.625 16.5,59.75 27.125,59.75 35.375,51.5 41.375,51.5 41.75,51.875 44,51.875 44.875,51 46.5,51 47.375,50.125 47.375,48.375 48.75,47 51.125,47 53.5,44.625 53.5,40.625 51.25,38.375 51.25,35.625 v1(50.875,35.25)
  Bottom Layer w0.125: v1(50.875,35.25) 50.875,34.645 R97.2@51.02,34.5
LVDS0_I2C_SDA: J19.18 R98.2 | length 42.9
  Top Layer w0.125: v1(12.375,63.875) J19.18@12.375,65.2
  Layer 5 w0.125: v1(12.375,63.875) 12.375,63.375 16.25,59.5 26.75,59.5 35,51.25 40.875,51.25 42.375,49.75 46,49.75 v1(46.75,49)
  Bottom Layer w0.125: v1(46.75,49) 47.48,49 R98.2@47.5,48.98
LVDS0_IRQ_N: J19.19 R76.2 U1.M3 | length 55.3
  Top Layer w0.125: v1(11.125,63.875) J19.19@11.125,65.2 ; v1(50.5,40.5) U1.M3@51.5,40.5
  Layer 5 w0.125: v1(11.125,63.875) 11.125,62.125 14.375,58.875 21,58.875 29,50.875 38.25,50.875 39.625,49.5 39.625,46.625 42.375,43.875 45,43.875 45.125,44 46.75,44 47.625,43.125 48.5,43.125 50.5,41.125 v1(50.5,40.5)
  Bottom Layer w0.125: v1(11.125,63.875) R76.2@11.125,64.645
LVDS0_TX0_N: J19.2 U1.J4 | length 39.6
  Top Layer w0.122: v1(32.125,68.125) 31.872,67.872 31.872,66.278 32.375,65.775 J19.2@32.375,65.2 ; v1(53,47.125) U1.J4@53.5,46.5
  Layer 10 w0.101: v1(32.125,68.125) 31.9,68.35 31.9,68.476 32.124,68.7 37.001,68.7 39.451,66.25 41.701,66.25 49.162,58.789 49.162,54.463 51.325,52.3 51.325,48.151 52.126,47.35 52.775,47.35 v1(53,47.125)
LVDS0_TX0_P: J19.3 U1.H4 | length 40.1
  Top Layer w0.122: J19.3@31.125,65.2 31.125,65.75 31.625,66.25 31.625,67.875 v1(31.375,68.125) ; v1(53,47.875) U1.H4@53.5,48.5
  Layer 10 w0.101: v1(31.375,68.125) 31.6,68.35 31.6,68.6 32,69 37.125,69 39.575,66.55 41.825,66.55 49.462,58.913 49.462,54.587 51.625,52.424 51.625,48.275 52.25,47.65 52.775,47.65 v1(53,47.875)
LVDS0_TX1_N: J19.5 U1.F4 | length 41.9
  Top Layer w0.122: v1(28.375,66.5) 28.375,65.45 J19.5@28.625,65.2 ; U1.F4@53.5,52.5 v1(54,53.125)
  Layer 10 w0.101: v1(28.375,66.5) 28.15,66.725 28.15,68.025 29.575,69.45 41.501,69.45 43.951,67 46.95,67 51.325,62.625 51.325,54.376 52.351,53.35 53.775,53.35 v1(54,53.125)
LVDS0_TX1_P: J19.6 U1.E4 | length 42.4
  Top Layer w0.122: J19.6@27.375,65.2 27.625,65.45 v1(27.625,66.5) ; U1.E4@53.5,54.5 v1(54,53.875)
  Layer 10 w0.101: v1(27.625,66.5) 27.85,66.725 27.85,68.149 29.451,69.75 41.625,69.75 44.075,67.3 47.074,67.3 51.625,62.749 51.625,54.5 52.475,53.65 53.775,53.65 v1(54,53.875)
LVDS0_TX2_N: J19.8 U1.C4 | length 43.7
  Top Layer w0.122: v1(24.625,66.5) 24.625,65.45 J19.8@24.875,65.2 ; U1.C4@53.5,58.5 v1(54,59.125)
  Layer 10 w0.101: v1(24.625,66.5) 24.4,66.725 24.4,67.4 27.2,70.2 50.376,70.2 53.663,66.913 53.663,61.337 52.95,60.624 52.95,59.776 53.376,59.35 53.775,59.35 v1(54,59.125)
LVDS0_TX2_P: J19.9 U1.B4 | length 44.2
  Top Layer w0.122: J19.9@23.625,65.2 23.875,65.45 v1(23.875,66.5) ; U1.B4@53.5,60.5 v1(54,59.875)
  Layer 10 w0.101: v1(23.875,66.5) 24.1,66.725 24.1,67.524 27.076,70.5 50.5,70.5 53.963,67.037 53.963,61.213 53.25,60.5 53.25,59.9 53.5,59.65 53.775,59.65 v1(54,59.875)
LVDS0_TX3_N: J19.14 U1.R4 | length 64.2
  Top Layer w0.122: v1(17.125,66.5) 17.125,65.45 J19.14@17.375,65.2 ; v1(53,35.125) U1.R4@53.5,34.5
  Layer 10 w0.101: v1(17.125,66.5) 16.9,66.725 16.9,67.375 17.4,67.875 18.25,67.875 19.125,67 19.125,63.251 20.926,61.45 28.55,61.45 28.75,61.25 41.701,61.25 45.35,57.601 45.35,53.516 47.375,51.491 47.375,48.451 49.2,46.626 49.2,42.626 51.375,40.451 51.375,36.351 52.376,35.35 52.775,35.35 v1(53,35.125)
LVDS0_TX3_P: J19.15 U1.P4 | length 64.7
  Top Layer w0.122: J19.15@16.125,65.2 16.375,65.45 v1(16.375,66.5) ; v1(53,35.875) U1.P4@53.5,36.5
  Layer 10 w0.101: v1(16.375,66.5) 16.6,66.725 16.6,67.499 17.276,68.175 18.374,68.175 19.425,67.124 19.425,63.375 21.05,61.75 28.674,61.75 28.874,61.55 41.825,61.55 45.65,57.725 45.65,53.641 47.675,51.616 47.675,48.575 49.5,46.75 49.5,42.75 51.675,40.575 51.675,36.475 52.5,35.65 52.775,35.65 v1(53,35.875)
LVDS1_CLK_N: J31.10 U1.E1 | length 58.6
  Top Layer w0.122: v1(47,53.875) U1.E1@47.5,54.5
  Layer 3 w0.101: J31.10@2.125,39.125 2.6,38.65 6.275,38.65 7.55,39.925 24.874,39.925 26.499,38.3 28.499,38.3 29.749,37.05 31.925,37.05 37.175,42.3 38.501,42.3 39.875,43.674 39.875,50.549 41.626,52.3 43.175,52.3 44.525,53.65 46.775,53.65 v1(47,53.875)
LVDS1_CLK_P: J31.9 U1.F1 | length 58.6
  Top Layer w0.122: v1(47,53.125) U1.F1@47.5,52.5
  Layer 3 w0.101: J31.9@2.125,37.875 2.6,38.35 6.399,38.35 7.674,39.625 24.75,39.625 26.375,38 28.375,38 29.625,36.75 32.049,36.75 37.299,42 38.625,42 40.175,43.55 40.175,50.425 41.75,52 43.299,52 44.649,53.35 46.775,53.35 v1(47,53.125)
LVDS1_CONTRAST: J31.13 U1.V13 | length 134.3
  Top Layer w0.125: J31.13@2.125,42.875 3.625,41.375 3.625,14.25 5.375,12.5 5.75,12.5 v1(6.25,12) ; U1.V13@71.5,28.5 v1(72.125,29.125)
  Layer 5 w0.125: v1(6.25,12) 7,12 8,13 9.875,13 10.125,12.75 23.229,12.75 26.104,15.625 28.75,15.625 29.375,15 38.625,15 39.25,15.625 43,15.625 45.125,13.5 45.125,8.125 49,4.25 59.75,4.25 60.375,4.875 60.375,10.793 61.957,12.375 64.75,12.375 66.25,10.875 v1(70.25,10.875)
  Layer 3 w0.125: v1(70.25,10.875) 70.25,14.375 70.875,15 70.875,18.375 71.5,19 71.5,24.25 72.125,24.875 v1(72.125,29.125)
LVDS1_IRQ_N: J31.12 R118.2 U1.AC20 | length 136
  Top Layer w0.125: J31.12@2.125,41.625 3.125,40.625 3.125,14.375 v1(5.5,12) ; v1(84.625,18.5) U1.AC20@85.5,18.5
  Layer 5 w0.125: v1(5.5,12) 6,12.5 6.875,12.5 7.625,13.25 10.125,13.25 10.375,13 23.125,13 26,15.875 29,15.875 29.625,15.25 38.521,15.25 39.125,15.854 39.125,15.875 43.125,15.875 45.375,13.625 45.375,8.25 49.125,4.5 59.625,4.5 60.125,5 60.125,10.896 61.854,12.625 64.875,12.625 66.125,11.375 78.271,11.375 81.896,15 82.625,15 84.625,17 v1(84.625,18.5)
  Bottom Layer w0.125: J31.12@2.125,41.625 R118.2@5.73,41.625
LVDS1_TX0_N: J31.2 U1.H1 | length 60
  Top Layer w0.122: v1(46.75,47.875) U1.H1@47.5,48.5
  Bottom Layer w0.122: J31.2@2.125,29.125 2.622,28.627 3,28.627 3.5,29.128 3.5,35.611 10.269,42.38 18.255,42.38 19.755,43.88 24.255,43.88 30.875,50.5 38.5,50.5 41.125,47.875 45.377,47.875 45.625,47.628 46.503,47.628 v1(46.75,47.875)
LVDS1_TX0_P: J31.1 U1.J1 | length 60
  Top Layer w0.122: v1(46.75,47.125) U1.J1@47.5,46.5
  Bottom Layer w0.122: J31.1@2.125,27.875 2.622,28.372 3.106,28.372 3.755,29.022 3.755,35.505 10.375,42.125 18.361,42.125 19.861,43.625 24.361,43.625 30.973,50.237 38.402,50.237 41.019,47.62 45.272,47.62 45.519,47.373 46.503,47.373 v1(46.75,47.125)
LVDS1_TX1_N: J31.4 U1.M1 | length 64.9
  Top Layer w0.122: v1(46.625,41.125) 46.872,41.373 47.375,41.373 47.5,41.247 U1.M1@47.5,40.5
  Layer 8 w0.101: J31.4@2.125,31.625 2.6,31.15 3.499,31.15 4.175,30.474 4.175,27.2 4.75,26.625 7.25,26.625 11,30.375 11,33.038 9.75,34.288 8.038,34.288 v1(7.875,34.125)
  Bottom Layer w0.122: v1(7.875,34.125) 8.06,34.31 14.671,34.31 19.986,39.625 22.486,39.625 24.831,41.97 39.78,41.97 40.125,41.625 45.392,41.625 45.644,41.373 46.377,41.373 v1(46.625,41.125)
LVDS1_TX1_P: J31.3 U1.L1 | length 65.9
  Top Layer w0.122: v1(46.625,41.875) 46.872,41.628 47.375,41.628 47.5,41.753 U1.L1@47.5,42.5
  Layer 8 w0.101: J31.3@2.125,30.375 2.6,30.85 3.375,30.85 3.875,30.35 3.875,27.076 4.626,26.325 7.374,26.325 11.3,30.251 11.3,33.162 9.874,34.588 8.037,34.588 v1(7.875,34.75)
  Bottom Layer w0.122: v1(7.875,34.75) 8.06,34.565 14.565,34.565 19.88,39.88 22.38,39.88 24.725,42.225 39.886,42.225 40.231,41.88 45.498,41.88 45.75,41.628 46.378,41.628 v1(46.625,41.875)
LVDS1_TX2_N: J31.6 U1.P1 | length 52.4
  Top Layer w0.122: v1(47,35.875) U1.P1@47.5,36.5
  Layer 3 w0.101: J31.6@2.125,34.125 2.6,33.65 3.375,33.65 5.6,35.875 21.999,35.875 22.999,34.875 28,34.875 30.875,32 35.25,32 36.125,31.125 43.875,31.125 44.7,31.95 44.7,34.724 45.626,35.65 46.775,35.65 v1(47,35.875)
LVDS1_TX2_P: J31.5 U1.R1 | length 52.4
  Top Layer w0.122: v1(47,35.125) U1.R1@47.5,34.5
  Layer 3 w0.101: J31.5@2.125,32.875 2.6,33.35 3.499,33.35 5.724,35.575 21.875,35.575 22.875,34.575 27.876,34.575 30.751,31.7 35.126,31.7 36.001,30.825 43.999,30.825 45,31.826 45,34.6 45.75,35.35 46.775,35.35 v1(47,35.125)
LVDS1_TX3_N: J31.8 U1.U1 | length 62.3
  Top Layer w0.122: v1(47,29.875) U1.U1@47.5,30.5
  Layer 10 w0.101: J31.8@2.125,36.625 2.6,36.15 14.649,36.15 20.674,30.125 26.5,30.125 29.3,32.925 30.3,32.925 32.875,35.5 38.875,35.5 39.95,36.575 39.95,37.624 42.251,39.925 44.2,39.925 45,39.125 45,30.799 46.149,29.65 46.775,29.65 v1(47,29.875)
LVDS1_TX3_P: J31.7 U1.V1 | length 62.3
  Top Layer w0.122: v1(47,29.125) U1.V1@47.5,28.5
  Layer 10 w0.101: J31.7@2.125,35.375 2.6,35.85 14.525,35.85 20.55,29.825 26.624,29.825 29.424,32.625 30.424,32.625 32.999,35.2 38.999,35.2 40.25,36.451 40.25,37.5 42.375,39.625 44.076,39.625 44.7,39.001 44.7,30.951 44.7,30.675 46.025,29.35 46.775,29.35 v1(47,29.125)
MCA_RESET_N: J11.10 U1.N23 | length 117.5
  Top Layer w0.125: J11.10@13.822,57.625 v1(15.625,57.625) ; U1.N23@91.5,38.5 v1(91.5,39.5)
  Layer 8 w0.125: v1(15.625,57.625) 17,59 17,63.125 18.875,65 18.875,67.875 20.375,69.375 61,69.375 61.625,70 64.25,70 64.625,69.625 75.125,69.625 77.75,67 87.875,67 91,63.875 91,52.5 88.5,50 88.5,44.5 90.125,42.875 90.125,39.75 90.625,39.25 91.25,39.25 v1(91.5,39.5)
MCA_SWD_CLK: J11.4 U1.L23 | length 112.2
  Top Layer w0.125: J11.4@13.802,61.375 v1(15.625,61.375) ; v1(90.875,43.125) U1.L23@91.5,42.5
  Layer 8 w0.125: v1(15.625,61.375) 15.125,61.875 15.125,63.125 15.375,63.375 15.375,67 18.875,70.5 75.375,70.5 78,67.875 88.75,67.875 92.375,64.25 92.375,52.5 90,50.125 90,44 v1(90.875,43.125)
MCA_SWD_DIO: J11.2 U1.M23 | length 111.5
  Top Layer w0.125: J11.2@13.822,62.625 v1(15.625,62.625) ; v1(90.875,39.875) U1.M23@91.5,40.5
  Layer 8 w0.125: v1(15.625,62.625) 18.125,65.125 18.125,67.625 20.25,69.75 60.875,69.75 61.375,70.25 64.5,70.25 64.875,69.875 75.25,69.875 77.875,67.25 88.125,67.25 91.375,64 91.375,52.5 89.5,50.625 89.5,48.875 89,48.375 89,44.375 90.375,43 90.375,40.375 v1(90.875,39.875)
MIC_BIAS: J26.1 L23.1 | length 7.2
  Bottom Layer w0.125: J26.1@63.625,11.375 63.625,15.375 64.75,16.5 L23.1@64.75,18.145
MIC_IN: J26.2 L22.1 | length 8.9
  Bottom Layer w0.125: J26.2@63.765,10.125 64.625,10.985 64.625,14.75 65.875,16 L22.1@65.875,18.145
NetC4_2: C4.2 R15.2 U6.1 U6.2 | length 5.1
  Bottom Layer w0.125: R15.2@79.5,26.7 79.5,26.125 79.875,25.75 80.25,25.75 80.5,25.5 v1(80.5,25.125) 80.5,24.5 ; U6.2@79.6,24.5 80.5,24.5 ; U6.1@79.6,25.15 v1@80.475,25.15 ; C4.2@81.04,24.5 80.5,24.5
NetC8_1: C8.1 C9.2 C10.2 R20.2 R21.1 R23.2 U7.7 | length 16.4
  Top Layer w0.25: v1(87.96,33.5) 88.75,34.29 v1(88.75,36) 88.75,36.5 88.275,36.975 88.275,38.15 v1(88.625,38.5)
  Bottom Layer w0.25: R23.2@85.98,34.5 86.98,33.5 v1(87.96,33.5) ; C10.2@87.96,34.5 v1(87.96,33.5) ; R20.2@87.98,38.5 v1(88.625,38.5) 88.625,39.55 C8.1@90.575,41.5 ; U7.7@88,36.275 88.475,36.275 v1(88.75,36) ; R21.1@89.02,32.5 C9.2@87.96,32.5 v1(87.96,33.5)
NetC18_1: C18.1 U8.28 | length 2.2
  Top Layer w0.125: U8.28@20,62.297 v1(20,63.625)
  Bottom Layer w0.125: C18.1@20,62.71 v1(20,63.625)
NetC18_2: C18.2 U8.24 | length 5.2
  Top Layer w0.125: v1(22.625,60.875) U8.24@22.625,62.228
  Bottom Layer w0.125: C18.2@20,61.79 20,61 20.625,60.375 22.125,60.375 v1(22.625,60.875)
NetC19_2: C19.2 U8.27 | length 2.5
  Top Layer w0.125: U8.27@20.697,62.25 20.697,63.322 v1(21,63.625)
  Bottom Layer w0.125: v1(21,63.625) 21.25,63.375 C19.2@21.25,62.71
NetC20_1: C20.1 U9.28 | length 6
  Top Layer w0.125: v1(34.5,60) U9.28@34.5,61.975
  Bottom Layer w0.125: v1(34.5,60) 36.625,60 37.337,60.712 37.337,61.502 C20.1@37.375,61.54
NetC20_2: C20.2 U9.24 | length 2.4
  Top Layer w0.125: U9.24@37.125,62 v1(37.125,63.375)
  Bottom Layer w0.125: v1(37.125,63.375) 37.375,63.125 C20.2@37.375,62.46
NetC21_2: C21.2 U9.27 | length 2.3
  Top Layer w0.125: v1(35.125,60.625) U9.27@35.125,61.95
  Bottom Layer w0.125: C21.2@34.875,61.54 34.875,60.875 v1(35.125,60.625)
